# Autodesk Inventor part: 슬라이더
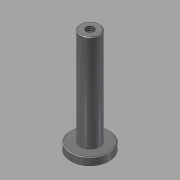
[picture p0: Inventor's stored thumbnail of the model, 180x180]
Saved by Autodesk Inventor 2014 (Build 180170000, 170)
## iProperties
Created: 2016-02
Part Number: 슬라이더
Material: 스테인리스강
Document SubType Name: Modeling
Designer: mduedu
Density: 8.08 g/cm^3
Appearance: 반광택
Mass: 71.0022 g
Surface Area: 36.7606 cm^2
Volume: 8.78741 cm^3
Author: mduedu
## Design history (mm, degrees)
sketch "스케치1"
  geometry: C1 r 12 at (0, 0); 1 further point
  constraints: 1 centre point, 1 coincident
  dimensions: "d0" = 24 diameter of C1
extrude "돌출1" new body sketch "스케치1" distance "d1" = 5; taper "d2" = 0 deg
sketch "스케치2"
  geometry: C1 r 6 at (0, 0); 1 further point
  constraints: 1 centre point, 1 coincident
  dimensions: "d3" = 12 diameter of C1
extrude "돌출2" join sketch "스케치2" distance "d4" = 60; taper "d5" = 0 deg
chamfer "모따기1" distance "d6" = 0.5; stored, may be unused: second distance "d7" = 2, angle "d8" = 45 deg
hole "구멍1" diameter "d11" = 4.917; stored, may be unused: countersink angle "d15" = 90 deg, drill point angle "d17" = 118 deg; dims "d9" = 10, "d10" = 10, "d12" = 10, "d13" = 4, "d14" = 2, "d16" = 12
chamfer "모따기2" distance "d18" = 0.5; stored, may be unused: second distance "d19" = 2, angle "d20" = 45 deg
node "솔리드1"
